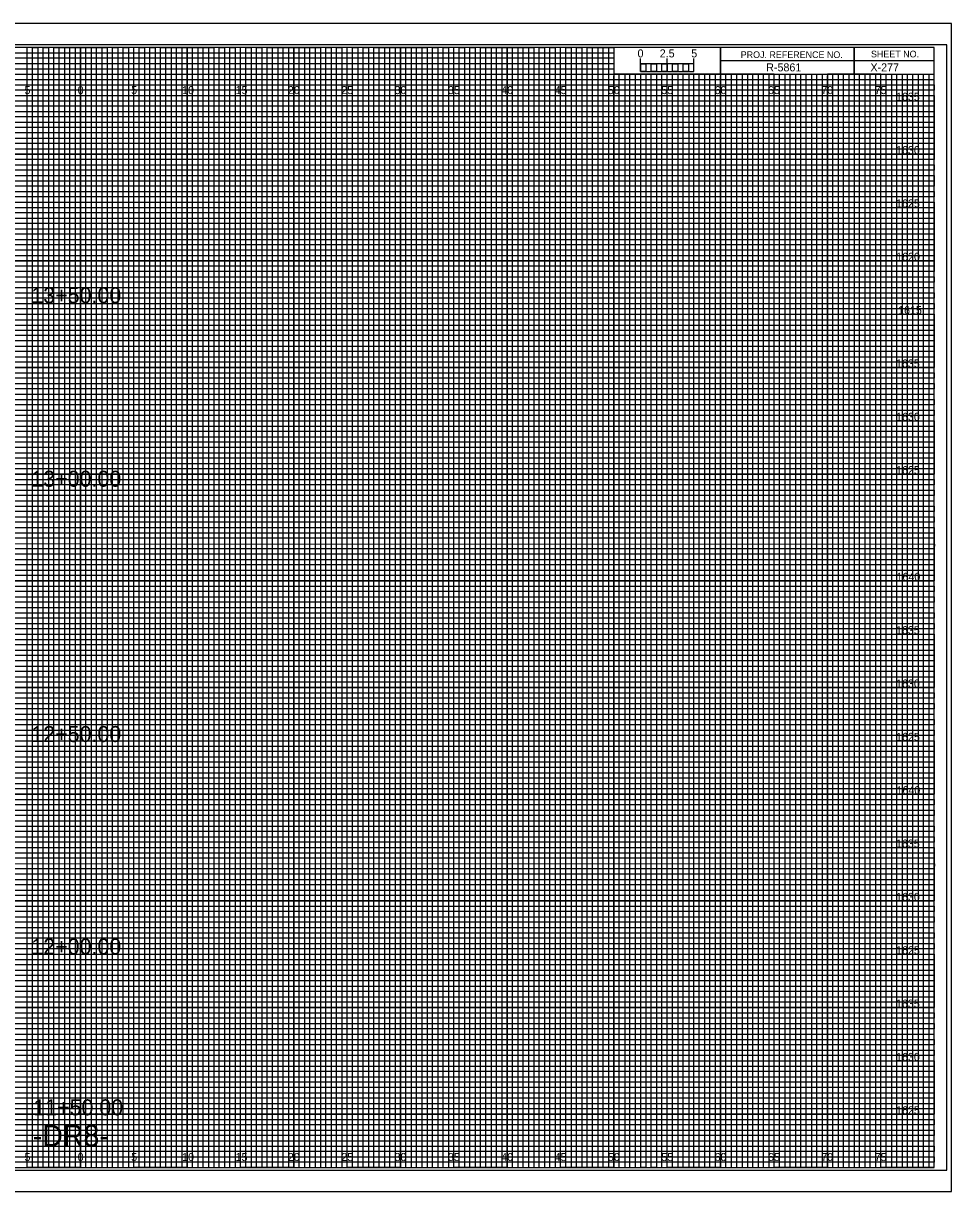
# Model space of a CAD drawing. Extents: x -7 to 162, y -2 to 107.
# Drawn here: x 74.6 to 161.7, y -2.3 to 107.3 of the extents above; entities that cross this region are included whole.
import ezdxf

# ---------------------------------------------------------------- set-up
doc = ezdxf.new("R2010")
doc.units = 0
for name, color, linetype in [('Prop XS Alignment Label', 7, 'Continuous'), ('Prop XS Bar Scale Labels', 7, 'Continuous'), ('Prop XS Elevation Labels', 7, 'Continuous'), ('Prop XS Offset Labels', 7, 'Continuous'), ('Prop XS Project Number', 7, 'Continuous'), ('Prop XS Sheet Number', 7, 'Continuous'), ('Prop XS Station Labels', 7, 'Continuous'), ('Sheet Cross Section CELL', 7, 'Continuous'), ('Sheet Cross Section Grid Major CELL', 7, 'Continuous'), ('Sheet Cross Section Grid Middle CELL', 7, 'Continuous'), ('Sheet Cross Section Grid Minor 1 CELL', 7, 'Continuous'), ('Sheet Cross Section Grid Minor 2 CELL', 7, 'Continuous'), ('Sheet Cross Section Scale CELL', 7, 'Continuous'), ('Sheet Cutting Line CELL', 7, 'Continuous'), ('Sheet DOT Grid CELL', 7, 'Continuous'), ('Sheet Plot Border Inside CELL', 7, 'Continuous'), ('Sheet Plot Border Outside CELL', 7, 'Continuous')]:
    doc.layers.add(name, color=color, linetype=linetype)

msp = doc.modelspace()

# ---------------------------------------------------------------- linework, layer by layer
at = {"layer": 'Sheet Cross Section CELL'}
for p, q in [((152.5, 105), (152.5, 102.5)), ((152.5, 102.5), (152.5, 105)), ((160, 103.75), (140, 103.75)), ((140, 103.75), (140, 102.5)), ((140, 102.5), (160, 102.5))]:
    msp.add_line(p, q, dxfattribs=at)
for points in [[(160, 105), (0, 105), (0, 0), (160, 0)], [(140, 105), (130, 105), (130, 102.52), (140, 102.52)], [(160, 105), (140, 105), (140, 102.5), (160, 102.5)]]:
    msp.add_lwpolyline(points, close=True, dxfattribs=at)
at = {"layer": 'Sheet Cross Section Grid Major CELL'}
for p, q in [((75, 105), (70, 105)), ((75, 0), (75, 105)), ((85, 105), (80, 105)), ((80, 105), (80, 0)), ((85, 0), (85, 105)), ((95, 105), (90, 105)), ((90, 105), (90, 0)), ((95, 0), (95, 105)), ((105, 105), (100, 105)), ((100, 105), (100, 0)), ((105, 0), (105, 105)), ((115, 105), (110, 105)), ((110, 105), (110, 0)), ((115, 0), (115, 105)), ((125, 105), (120, 105)), ((120, 105), (120, 0)), ((125, 0), (125, 105)), ((130, 105), (130, 0)), ((135, 0), (135, 102.5)), ((145, 102.5), (140, 102.5)), ((140, 102.5), (140, 0)), ((145, 0), (145, 102.5)), ((155, 102.5), (150, 102.5)), ((150, 102.5), (150, 0)), ((155, 0), (155, 102.5)), ((80, 0), (75, 0)), ((90, 0), (85, 0)), ((100, 0), (95, 0)), ((110, 0), (105, 0)), ((120, 0), (115, 0)), ((130, 0), (125, 0)), ((140, 0), (135, 0)), ((150, 0), (145, 0)), ((160, 0), (155, 0)), ((160, 0), (160, 0))]:
    msp.add_line(p, q, dxfattribs=at)
for points in [[(0, 100), (160, 100), (160, 95), (0, 95)], [(0, 90), (160, 90), (160, 85), (0, 85)], [(0, 80), (160, 80), (160, 75), (0, 75)], [(0, 70), (160, 70), (160, 65), (0, 65)], [(0, 60), (160, 60), (160, 55), (0, 55)], [(0, 50), (160, 50), (160, 45), (0, 45)], [(0, 40), (160, 40), (160, 35), (0, 35)], [(0, 30), (160, 30), (160, 25), (0, 25)], [(0, 20), (160, 20), (160, 15), (0, 15)], [(0, 10), (160, 10), (160, 5), (0, 5)]]:
    msp.add_lwpolyline(points, dxfattribs=at)
at = {"layer": 'Sheet Cross Section Grid Middle CELL'}
for points in [[(72.5, 0), (77.5, 0), (77.5, 105), (82.5, 105), (82.5, 0), (87.5, 0), (87.5, 105), (92.5, 105), (92.5, 0), (97.5, 0), (97.5, 105), (102.5, 105), (102.5, 0), (107.5, 0), (107.5, 105), (112.5, 105), (112.5, 0), (117.5, 0), (117.5, 105), (122.5, 105), (122.5, 0), (127.5, 0), (127.5, 105), (129.97, 105), (130, 105), (130, 102.5), (132.5, 102.5), (132.5, 0), (137.5, 0), (137.5, 102.5), (142.5, 102.5), (142.5, 0), (147.5, 0), (147.5, 102.5), (152.5, 102.5), (152.5, 0), (157.5, 0), (157.5, 102.5)], [(0, 102.5), (137.5, 102.5)], [(0, 92.5), (160, 92.5), (160, 97.5), (0, 97.5)], [(0, 82.5), (160, 82.5), (160, 87.5), (0, 87.5)], [(0, 72.5), (160, 72.5), (160, 77.5), (0, 77.5)], [(0, 62.5), (160, 62.5), (160, 67.5), (0, 67.5)], [(0, 52.5), (160, 52.5), (160, 57.5), (0, 57.5)], [(0, 42.5), (160, 42.5), (160, 47.5), (0, 47.5)], [(0, 32.5), (160, 32.5), (160, 37.5), (0, 37.5)], [(0, 22.5), (160, 22.5), (160, 27.5), (0, 27.5)], [(0, 12.5), (160, 12.5), (160, 17.5), (0, 17.5)], [(0, 2.5), (160, 2.5), (160, 7.5), (0, 7.5)]]:
    msp.add_lwpolyline(points, dxfattribs=at)
at = {"layer": 'Sheet Cross Section Grid Minor 1 CELL'}
for p, q in [((0, 104.5), (130, 104.5)), ((130, 104.5), (130, 103.99)), ((130, 103.99), (0, 103.99)), ((0, 103.5), (130, 103.5)), ((130, 102.95), (0, 102.95)), ((130, 103.5), (130, 102.95)), ((0, 102), (160, 102))]:
    msp.add_line(p, q, dxfattribs=at)
for points in [[(0, 101.5), (135, 101.5), (160, 101.5), (160, 101), (0, 101)], [(0, 100.5), (160, 100.5), (160, 99.5), (0, 99.5)], [(0, 99), (160, 99), (160, 98.5), (0, 98.49)], [(0, 98), (160, 98), (160, 97), (0, 97)], [(0, 96.5), (160, 96.5), (160, 96), (0, 96)], [(0, 95.5), (160, 95.5), (160, 94.5), (0, 94.5)], [(0, 94), (160, 94), (160, 93.5), (0, 93.5)], [(0, 93), (160, 93), (160, 92), (0, 92)], [(0, 91.5), (160, 91.5), (160, 91), (0, 91)], [(0, 90.5), (160, 90.5), (160, 89.5), (0, 89.5)], [(0, 89), (160, 89), (160, 88.5), (0, 88.5)], [(0, 88), (160, 88), (160, 86.98), (160, 86.5), (160, 86), (0, 86)], [(0, 87), (160, 87), (160, 86.5), (0, 86.5)], [(0, 85.5), (160, 85.5), (160, 84.5), (0, 84.52)], [(0, 84.52), (160, 84.5), (160, 84), (0, 84)], [(0, 83.5), (160, 83.5), (160, 83), (0, 83)], [(0, 82), (160, 82), (160, 81.5), (0, 81.5)], [(0, 81), (160, 81), (160, 80.5), (0, 80.5)], [(-0.04, 79.45), (160, 79.45), (160, 78.94), (-0.04, 78.94)], [(0, 78.5), (160, 78.5), (160, 78), (0, 78)], [(0, 77), (160, 77), (160, 76.5), (0, 76.5)], [(0, 76), (160, 76), (160, 75.5), (0, 75.5)], [(0, 74.5), (160, 74.5), (160, 74), (0, 74)], [(0, 73.5), (160, 73.5), (160, 73), (0, 73)], [(0, 72), (160, 72), (160, 71.5), (0, 71.5)], [(0, 71), (160, 71), (160, 70.5), (0, 70.5)], [(0, 69.5), (160, 69.5), (160, 68.99), (0, 69)], [(0, 68.5), (160, 68.5), (160, 68), (0, 68)], [(0, 67), (160, 67), (160, 66.5), (0, 66.5)], [(0, 66), (160, 66), (160, 65.5), (0, 65.5)], [(0, 64.5), (160, 64.5), (160, 64), (0, 64)], [(0, 63.5), (160, 63.5), (160, 63), (0, 63)], [(0, 62), (160, 62), (160, 61.5), (0, 61.5)], [(0, 61), (160, 61), (160, 60.5), (0, 60.5)], [(0, 59.5), (160, 59.5), (160, 59), (0, 59)], [(0, 58.5), (160.03, 58.45), (160, 58), (0, 58)], [(0, 57), (160, 57), (160, 56.5), (0, 56.5)], [(0, 56), (160, 56), (160, 55.5), (0, 55.5)], [(0, 54.5), (160, 54.5), (160, 54), (0, 54)], [(0, 53.5), (160, 53.5), (160, 53), (0, 53)], [(0, 52), (160, 52), (160, 51.5), (0, 51.5)], [(0, 51), (160, 51), (160, 50.5), (0, 50.5)], [(0, 49.5), (160, 49.5), (160, 49), (0, 49)], [(0, 48.5), (160, 48.5), (160, 48), (0, 48)], [(0, 47), (160, 47), (160, 46.5), (0, 46.5)], [(0, 46), (160, 46), (160, 45.5), (0, 45.5)], [(0, 44.5), (160, 44.5), (160, 44), (0, 44)], [(0, 43.5), (160, 43.5), (160, 43), (0, 43)], [(0, 42), (160, 42), (160, 41.5), (0, 41.5)], [(0, 41), (160, 41), (160, 40.5), (0, 40.5)], [(0, 39.5), (160, 39.5), (160, 38.99), (0, 39)], [(0, 38.5), (160, 38.5), (160, 38), (0, 38)], [(0, 37), (160, 37), (160, 36.5), (0, 36.5)], [(0, 36), (160, 36), (160, 35.5), (0, 35.5)], [(0, 34.5), (160, 34.5), (160, 34), (0, 34)], [(0, 33.5), (160, 33.5), (160, 33), (0, 33)], [(0, 32), (160, 32), (160, 31.5), (0, 31.5)], [(0, 31), (160, 31), (160, 30.5), (0, 30.5)], [(0, 29.5), (160, 29.5), (160, 29), (0, 29)], [(0, 28.5), (160.03, 28.46), (160, 28), (0, 28)], [(0, 27), (160, 27), (160, 26.5), (0, 26.5)], [(0, 26), (160, 26), (160, 25.5), (0, 25.5)], [(0, 24.5), (160, 24.5), (160, 24), (0, 24)], [(0, 23.5), (160, 23.5), (160, 23), (0, 23)], [(0, 22), (160, 22), (160, 21.5), (0, 21.5)], [(0, 21), (160, 21), (160, 20.5), (0, 20.5)], [(0, 19.5), (160, 19.5), (160, 19), (0, 19)], [(0, 18.5), (160, 18.5), (160, 18), (0, 18)], [(0, 17), (160, 17), (160, 16.5), (0, 16.5)], [(0, 16), (160, 16), (160, 15.5), (0, 15.5)], [(0, 14.5), (160, 14.5), (160, 14), (0, 14)], [(0, 13.5), (160, 13.5), (160, 13), (0, 13)], [(0, 12), (160, 12), (160, 11.5), (0, 11.5)], [(0, 11), (160, 11), (160, 10.5), (0, 10.5)], [(0, 9.5), (160, 9.5), (160, 9), (0, 9)], [(0, 8.5), (160, 8.5), (160, 8), (0, 8)], [(0, 7), (160, 7), (160, 6.5), (0, 6.5)], [(0, 6), (160, 6), (160, 5.5), (0, 5.5)], [(0, 4.5), (160, 4.5), (160, 4), (0, 4)], [(0, 3.5), (160, 3.5), (160, 3), (0, 3)], [(0, 2), (160, 2), (160, 1.5), (0, 1.5)], [(0, 1), (160, 1), (160, 0.5), (0, 0.5)]]:
    msp.add_lwpolyline(points, dxfattribs=at)
at = {"layer": 'Sheet Cross Section Grid Minor 2 CELL'}
for p, q in [((133.5, 102.5), (133, 102.5)), ((133, 102.5), (133, 0)), ((133.5, 0), (133.5, 102.5)), ((134.5, 102.5), (134, 102.5)), ((134, 102.5), (134, 0)), ((134.5, 0), (134.5, 102.5)), ((133, 0), (132.5, 0)), ((134, 0), (133.5, 0))]:
    msp.add_line(p, q, dxfattribs=at)
for points in [[(75, 0), (75.5, 0), (75.5, 105), (76, 105), (76, 0)], [(76, 0), (76.5, 0), (76.5, 105), (77, 105), (77, 0)], [(77.5, 0), (78, 0), (78, 105), (78.5, 105), (78.5, 0)], [(78.5, 0), (79, 0), (79, 105), (79.5, 105), (79.5, 0)], [(80, 0), (80.5, 0), (80.5, 105), (81, 105), (81, 0)], [(81, 0), (81.5, 0), (81.5, 105), (82, 105), (82, 0)], [(82.5, 0), (83, 0), (83, 105), (83.5, 105), (83.5, 0)], [(83.5, 0), (84, 0), (84, 105), (84.5, 105), (84.5, 0)], [(85, 0), (85.5, 0), (85.5, 105), (86, 105), (86, 0)], [(86, 0), (86.5, 0), (86.5, 105), (87, 105), (87, 0)], [(87.5, 0), (88, 0), (88, 105), (88.5, 105), (88.5, 0)], [(88.5, 0), (89, 0), (89, 105), (89.5, 105), (89.5, 0)], [(90, 0), (90.5, 0), (90.5, 105), (91, 105), (91, 0)], [(91, 0), (91.5, 0), (91.5, 105), (92, 105), (92, 0)], [(92.5, 0), (93, 0), (93, 105), (93.5, 105), (93.5, 0)], [(93.5, 0), (94, 0), (94, 105), (94.5, 105), (94.5, 0)], [(95, 0), (95.5, 0), (95.5, 105), (96, 105), (96, 0)], [(96, 0), (96.5, 0), (96.5, 105), (97, 105), (97, 0)], [(97.5, 0), (98, 0), (98, 105), (98.5, 105), (98.5, 0)], [(98.5, 0), (99, 0), (99, 105), (99.5, 105), (99.5, 0)], [(100, 0), (100.5, 0), (100.5, 105), (101, 105), (101, 0)], [(101, 0), (101.5, 0), (101.5, 105), (102, 105), (102, 0)], [(102.5, 0), (103, 0), (103, 105), (103.5, 105), (103.5, 0)], [(103.5, 0), (104, 0), (104, 105), (104.5, 105), (104.5, 0)], [(105, 0), (105.5, 0), (105.5, 105), (106, 105), (106, 0)], [(106, 0), (106.5, 0), (106.5, 105), (107, 105), (107, 0)], [(107.5, 0), (108, 0), (108, 105), (108.5, 105), (108.5, 0)], [(108.5, 0), (109, 0), (109, 105), (109.5, 105), (109.5, 0)], [(110, 0), (110.5, 0), (110.5, 105), (111, 105), (111, 0)], [(111, 0), (111.5, 0), (111.5, 105), (112, 105), (112, 0)], [(112.5, 0), (113, 0), (113, 105), (113.5, 105), (113.5, 0)], [(113.5, 0), (114, 0), (114, 105), (114.5, 105), (114.5, 0)], [(115, 0), (115.5, 0), (115.5, 105), (116, 105), (116, 0)], [(116, 0), (116.5, 0), (116.5, 105), (117, 105), (117, 0)], [(117.5, 0), (118, 0), (118, 105), (118.5, 105), (118.5, 0)], [(118.5, 0), (119, 0), (119, 105), (119.5, 105), (119.5, 0)], [(120, 0), (120.5, 0), (120.5, 105), (121, 105), (121, 0)], [(121, 0), (121.5, 0), (121.5, 105), (122, 105), (122, 0)], [(122.5, 0), (123, 0), (123, 105), (123.5, 105), (123.5, 0)], [(123.5, 0), (124, 0), (124, 105), (124.5, 105), (124.5, 0)], [(125, 0), (125.5, 0), (125.5, 105), (126, 105), (126, 0)], [(126, 0), (126.5, 0), (126.5, 105), (127, 105), (127, 0)], [(127.5, 0), (128, 0), (128, 105), (128.5, 105), (128.5, 0)], [(128.5, 0), (129, 0), (129, 105), (129.5, 105), (129.5, 0)], [(130, 0), (130.5, 0), (130.5, 102.5), (131.01, 102.5), (131.01, 0)], [(131, 0), (131.5, 0), (131.5, 102.5), (132, 102.5), (132, 0)], [(135, 0), (135.49, 0), (135.49, 102.5), (136, 102.5), (136, 0)], [(136, 0), (136.5, 0), (136.5, 102.5), (137.03, 102.5), (137.03, 0)], [(137.5, 0), (138, 0), (138, 102.5), (138.5, 102.5), (138.5, 0)], [(138.5, 0), (139, 0), (139, 102.5), (139.5, 102.5), (139.5, 0)], [(140, 0), (140.5, 0), (140.5, 102.5), (141, 102.5), (141, 0)], [(141, 0), (141.5, 0), (141.5, 102.5), (142, 102.5), (142, 0)], [(142.5, 0), (143, 0), (143, 102.5), (143.5, 102.5), (143.5, 0)], [(143.5, 0), (144, 0), (144, 102.5), (144.5, 102.5), (144.5, 0)], [(145, 0), (145.5, 0), (145.5, 102.5), (146, 102.5), (146, 0)], [(146, 0), (146.5, 0), (146.5, 102.5), (147, 102.5), (147, 0)], [(147.5, 0), (148, 0), (148, 102.5), (148.5, 102.5), (148.5, 0)], [(148.5, 0), (149, 0), (149, 102.5), (149.5, 102.5), (149.5, 0)], [(150, 0), (150.5, 0), (150.5, 102.5), (151, 102.5), (151, 0)], [(151, 0), (151.5, 0), (151.5, 102.5), (152, 102.5), (152, 0)], [(152.5, 0), (153, 0), (153, 102.5), (153.5, 102.5), (153.5, 0)], [(153.5, 0), (154, 0), (154, 102.5), (154.5, 102.5), (154.5, 0)], [(155, 0), (155.5, 0), (155.5, 102.5), (156, 102.5), (156, 0)], [(156, 0), (156.5, 0), (156.5, 102.5), (157, 102.5), (157, 0)], [(157.5, 0), (158, 0), (158, 102.5), (158.5, 102.5), (158.5, 0)], [(158.5, 0), (159, 0), (159, 102.5), (159.5, 102.5), (159.5, 0)]]:
    msp.add_lwpolyline(points, dxfattribs=at)
at = {"layer": 'Sheet Cross Section Scale CELL'}
for p, q in [((132.5, 102.75), (132.5, 103.95)), ((132.5, 103.45), (132.5, 103.95)), ((135, 102.75), (135, 103.95)), ((137.5, 102.75), (137.5, 103.95)), ((137.5, 103.45), (137.5, 103.95))]:
    msp.add_line(p, q, dxfattribs=at)
for points in [[(137.5, 103.45), (132.5, 103.45), (132.5, 102.75), (137.5, 102.75)], [(132.5, 103.45), (133, 103.45), (133, 102.75), (132.5, 102.75)], [(133.5, 103.45), (134, 103.45), (134, 102.75), (133.5, 102.75)], [(134.5, 103.45), (135, 103.45), (135, 102.75), (134.5, 102.75)], [(135.5, 103.45), (136, 103.45), (136, 102.75), (135.5, 102.75)], [(136.5, 103.45), (137, 103.45), (137, 102.75), (136.5, 102.75)]]:
    msp.add_lwpolyline(points, close=True, dxfattribs=at)
at = {"layer": 'Sheet Cutting Line CELL'}
for p, q in [((161.65, 107.25), (-6.7, 107.25)), ((-6.7, -2.25), (161.65, -2.25))]:
    msp.add_line(p, q, dxfattribs=at)
at = {"layer": 'Sheet DOT Grid CELL'}
for p, q in [((75, 0), (75, 105)), ((80, 0), (80, 105)), ((85, 0), (85, 105)), ((90, 0), (90, 105)), ((95, 0), (95, 105)), ((100, 0), (100, 105)), ((105, 0), (105, 105)), ((110, 0), (110, 105)), ((115, 0), (115, 105)), ((120, 0), (120, 105)), ((125, 0), (125, 105)), ((130, 0), (130, 102.34)), ((135, 0), (135, 102.34)), ((140, 0), (140, 102.34)), ((145, 0), (145, 102.34)), ((150, 0), (150, 102.34)), ((155, 0), (155, 102.34)), ((0, 100), (160, 100)), ((0, 95), (160, 95)), ((0, 90), (160, 90)), ((0, 85), (160, 85)), ((0, 80), (160, 80)), ((0, 75), (160, 75)), ((0, 70), (160, 70)), ((0, 65), (160, 65)), ((0, 60), (160, 60)), ((0, 55), (160, 55)), ((0, 50), (160, 50)), ((0, 45), (160, 45)), ((0, 40), (160, 40)), ((0, 35), (160, 35)), ((0, 30), (160, 30)), ((0, 25), (160, 25)), ((0, 20), (160, 20)), ((0, 15), (160, 15)), ((0, 10), (160, 10)), ((0, 5), (160, 5))]:
    msp.add_line(p, q, dxfattribs=at)
at = {"layer": 'Sheet Plot Border Inside CELL'}
msp.add_lwpolyline([(-5.4, -0.25), (161.2, -0.25), (161.2, 105.25), (-5.4, 105.25)], close=True, dxfattribs=at)
at = {"layer": 'Sheet Plot Border Outside CELL'}
msp.add_lwpolyline([(-6.7, -2.25), (161.65, -2.25), (161.65, 107.25), (-6.7, 107.25)], close=True, dxfattribs=at)

# ---------------------------------------------------------------- texts
at = {"layer": 'Prop XS Alignment Label'}
msp.add_text('-DR8-', height=2, dxfattribs=at).set_placement((75.52, 2))
at = {"layer": 'Prop XS Bar Scale Labels'}
for s, p in [('2.5', (134.29, 104.06)), ('5', (137.24, 104.06))]:
    msp.add_text(s, height=0.75, dxfattribs=at).set_placement(p)
at = {"layer": 'Prop XS Elevation Labels'}
for s, p in [('1635', (156.43, 100)), ('1630', (156.44, 95)), ('1625', (156.44, 90)), ('1620', (156.45, 85)), ('1615', (156.63, 80)), ('1635', (156.43, 75)), ('1630', (156.44, 70)), ('1625', (156.44, 65)), ('1640', (156.48, 55)), ('1635', (156.43, 50)), ('1630', (156.44, 45)), ('1625', (156.44, 40)), ('1640', (156.48, 35)), ('1635', (156.43, 30)), ('1630', (156.44, 25)), ('1625', (156.44, 20)), ('1635', (156.43, 15)), ('1630', (156.44, 10)), ('1625', (156.44, 5))]:
    msp.add_text(s, height=0.75, dxfattribs=at).set_placement(p)
at = {"layer": 'Prop XS Offset Labels'}
for s, p in [('5', (74.74, 100.62)), ('0', (79.73, 100.62)), ('0', (79.73, 100.62)), ('5', (84.74, 100.62)), ('10', (89.52, 100.62)), ('15', (94.53, 100.62)), ('20', (99.43, 100.62)), ('25', (104.44, 100.62)), ('30', (109.43, 100.62)), ('35', (114.44, 100.62)), ('40', (119.43, 100.62)), ('45', (124.44, 100.62)), ('50', (129.43, 100.62)), ('55', (134.44, 100.62)), ('60', (139.43, 100.62)), ('65', (144.44, 100.62)), ('70', (149.43, 100.62)), ('75', (154.44, 100.62)), ('5', (74.74, 0.62)), ('0', (79.73, 0.62)), ('0', (79.73, 0.62)), ('5', (84.74, 0.62)), ('10', (89.52, 0.62)), ('15', (94.53, 0.62)), ('20', (99.43, 0.62)), ('25', (104.44, 0.62)), ('30', (109.43, 0.62)), ('35', (114.44, 0.62)), ('40', (119.43, 0.62)), ('45', (124.44, 0.62)), ('50', (129.43, 0.62)), ('55', (134.44, 0.62)), ('60', (139.43, 0.62)), ('65', (144.44, 0.62)), ('70', (149.43, 0.62)), ('75', (154.44, 0.62))]:
    msp.add_text(s, height=0.75, dxfattribs=at).set_placement(p)
at = {"layer": 'Prop XS Project Number'}
msp.add_text('R-5861', height=0.75, dxfattribs=at).set_placement((144.27, 102.75))
at = {"layer": 'Prop XS Sheet Number'}
msp.add_text('X-277', height=0.75, dxfattribs=at).set_placement((154.04, 102.75))
at = {"layer": 'Prop XS Station Labels'}
for s, p in [('13+50.00', (75.39, 81.02)), ('13+00.00', (75.39, 63.82)), ('12+50.00', (75.39, 39.89)), ('12+00.00', (75.39, 19.98)), ('11+50.00', (75.57, 4.9))]:
    msp.add_text(s, height=1.5, dxfattribs=at).set_placement(p)
at = {"layer": 'Sheet Cross Section CELL'}
for s, p in [('PROJ. REFERENCE NO.', (141.88, 104)), ('SHEET NO.', (154.09, 104.06))]:
    msp.add_text(s, height=0.625, dxfattribs=at).set_placement(p)
at = {"layer": 'Sheet Cross Section Scale CELL'}
msp.add_text('0', height=0.75, dxfattribs=at).set_placement((132.21, 104.06))

doc.saveas('drawing.dxf')
